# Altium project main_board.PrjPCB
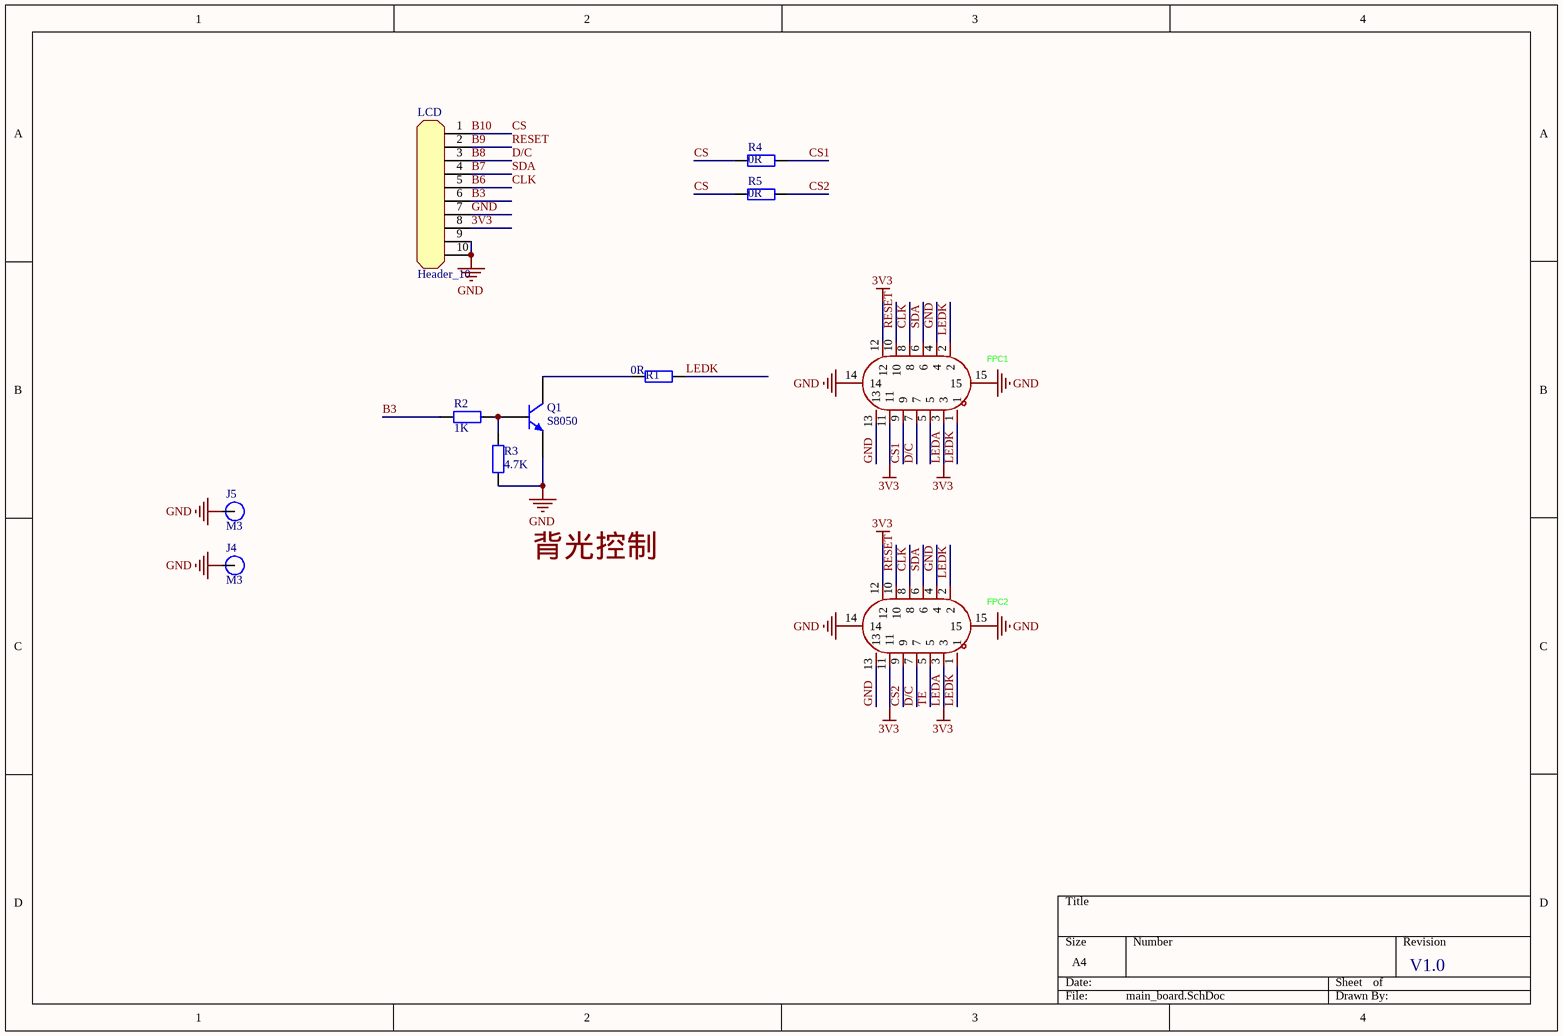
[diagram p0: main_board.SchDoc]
1 sheet, 11 parts. Net scope: global (net labels, ports and power ports of the same name join across sheets).
Board file: main_board.PcbDoc

## Sheet main_board.SchDoc
size A4

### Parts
FPC1  FH35C-13S-0.3SHW(50)  [FPC-SMD_13P-P0.60_HRS_FH35C-13S-0.3SHW]  (value not drawn)
FPC2  FH35C-13S-0.3SHW(50)  [FPC-SMD_13P-P0.60_HRS_FH35C-13S-0.3SHW]  (value not drawn)
J4  M3  [M3 125X200]
J5  M3  [M3 125X200]
LCD  Header_10  [CONN-SMD_SM08B-GHS-TB-LF-SN]
Q1  S8050  [SOT-23-3]
R1  0R  [R0402]
R2  1K  [R0402]
R3  4.7K  [R0402]
R4  0R  [R0603]
R5  0R  [R0603]

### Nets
3V3: FPC1.3 FPC1.11 FPC1.12 FPC2.3 FPC2.11 FPC2.12 LCD.8  [also labelled LEDA]
GND: FPC1.4 FPC1.13 FPC1.14 FPC1.15 FPC2.4 FPC2.13 FPC2.14 FPC2.15 J4.1(GND) J5.1(GND) LCD.7 LCD.9 LCD.10 Q1.2(E) R3.1
B3: LCD.6 R2.1
B6: FPC1.8 FPC2.8 LCD.5  [also labelled CLK]
B7: FPC1.6 FPC2.6 LCD.4  [also labelled SDA]
B8: FPC1.7 FPC2.7 LCD.3  [also labelled D/C]
B9: FPC1.10 FPC2.10 LCD.2  [also labelled RESET]
B10: LCD.1 R4.1 R5.1  [also labelled CS]
CS1: FPC1.9 R4.2
CS2: FPC2.9 R5.2
LEDK: FPC1.1 FPC1.2 FPC2.1 FPC2.2 R1.2
TE: FPC2.5
NetQ1_1: Q1.1(B) R2.2 R3.2
NetQ1_3: Q1.3(C) R1.1

Not connected (* = marked no-connect by the designer): FPC1 5

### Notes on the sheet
- 背光控制
- V1.0

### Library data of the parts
FPC1 FPC2 = FH35C-13S-0.3SHW(50)_C2889266: Manufacturer: HRS(广濑); Add into BOM: yes; Locking Feature: 翻盖式; Number of Contacts: 13P; Pitch: 0.3mm; FFC, FCB Thickness: 0.2mm
J4 J5 = M3: 铜柱孔; 版权归属: 源创客
LCD = 180DIP_PH_10: 01_物料名称: 排针; 02_规格参数: 单排针 1X10P 间距2.54mm 长度11mm 直针 黑色
Q1 = S8050: 01_物料名称: 三极管; 02_规格参数: NPN三极管-SOT-23-S8050-25V-500mA-300mW; 04_物料编码: 10060005
R1 = R0402/0R: 01_物料名称: 贴片电阻; 02_规格参数: 贴片电阻-0402-0R-±5%-1/16W; 04_物料编码: 10020002
R2 = R0402/1K: 01_物料名称: 贴片电阻; 02_规格参数: 贴片电阻-0402-1K±5%-1/16W; 04_物料编码: NC
R3 = R0402/4.7K: 01_物料名称: 贴片电阻; 02_规格参数: 贴片电阻-0402-4.7K±5%-1/16W; 04_物料编码: 10020008
R4 R5 = R0603/0R: 01_物料名称: 贴片电阻; 02_规格参数: 贴片电阻-0603-0R±5%-1/16W; 04_物料编码: 10020010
